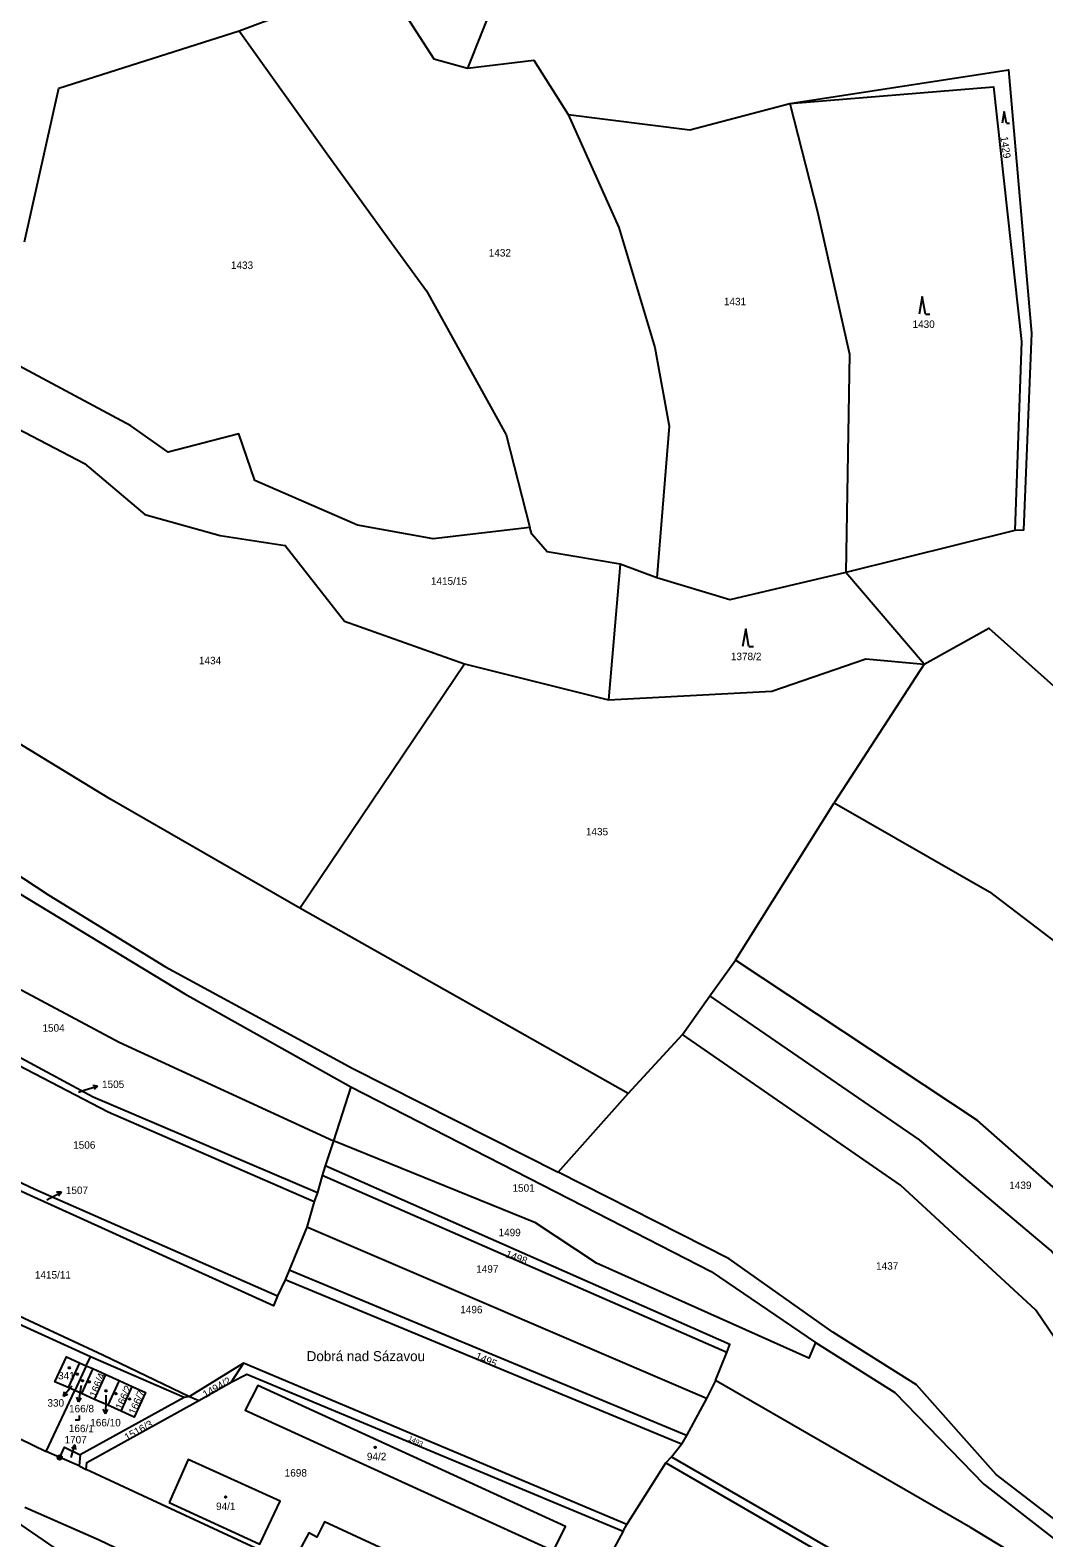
# Model space of a CAD drawing. Extents: x -680203 to -673936, y -1102717 to -1093650.
# Drawn here: x -675720.6 to -675489.7, y -1101094.1 to -1100750.7 of the extents above; entities that cross this region are included whole.
import ezdxf

# ---------------------------------------------------------------- set-up
doc = ezdxf.new("R2010")
doc.units = 0
for name, color, linetype in [('SOxx02xx_Koleje_param další_Popis10', 7, 'Continuous'), ('SOxx02xx_Staničení_Popis10', 7, 'Continuous'), ('SOxxxxxx_Koleje_hlavní_body_Popis10', 7, 'Continuous'), ('SOxxxxxx_Koleje_param další_Popis10', 7, 'Continuous'), ('SOxxxxxx_Osa_bod_P', 7, 'Continuous'), ('x_prac', 7, 'Continuous')]:
    doc.layers.add(name, color=color, linetype=linetype)

msp = doc.modelspace()

# ---------------------------------------------------------------- linework, layer by layer
at = {"layer": 'SOxx02xx_Koleje_param další_Popis10'}
for radius in [0.5, 0.0303]:
    msp.add_circle((-675713.86, -1101075.81), radius, dxfattribs=at)
at = {"layer": 'SOxx02xx_Staničení_Popis10'}
for p, q in [((-675708.09, -1100992.11), (-675705.22, -1100991.23)), ((-675705.22, -1100991.23), (-675706.32, -1100991.05)), ((-675705.22, -1100991.23), (-675706.03, -1100992)), ((-675709.61, -1100992.57), (-675708.09, -1100992.11)), ((-675716.12, -1101016.76), (-675713.45, -1101015.4)), ((-675713.45, -1101015.4), (-675714.57, -1101015.41)), ((-675713.45, -1101015.4), (-675714.11, -1101016.3)), ((-675716.76, -1101017.09), (-675716.12, -1101016.76)), ((-675711.08, -1101059.56), (-675713.01, -1101061.86)), ((-675709.13, -1101060.15), (-675709.6, -1101063.11)), ((-675709.01, -1101059.41), (-675709.13, -1101060.15)), ((-675713.01, -1101061.86), (-675712.75, -1101060.77)), ((-675713.01, -1101061.86), (-675711.98, -1101061.41)), ((-675709.6, -1101063.11), (-675709.94, -1101062.05)), ((-675709.6, -1101063.11), (-675708.95, -1101062.2)), ((-675703.39, -1101062.84), (-675703.44, -1101065.84)), ((-675703.38, -1101061.61), (-675703.39, -1101062.84)), ((-675703.44, -1101065.84), (-675703.93, -1101064.83)), ((-675703.44, -1101065.84), (-675702.92, -1101064.85)), ((-675711.26, -1101075.8), (-675710.43, -1101072.92)), ((-675710.43, -1101072.92), (-675711.19, -1101073.74)), ((-675710.43, -1101072.92), (-675710.23, -1101074.02))]:
    msp.add_line(p, q, dxfattribs=at)
at = {"layer": 'SOxxxxxx_Koleje_hlavní_body_Popis10'}
for p, q in [((-675498.75, -1100769.25), (-675499.25, -1100771.93)), ((-675498.25, -1100771.93), (-675498.75, -1100769.25)), ((-675498.25, -1100771.93), (-675497.58, -1100771.93)), ((-675517.41, -1100811.41), (-675518.16, -1100815.41)), ((-675516.66, -1100815.41), (-675517.41, -1100811.41)), ((-675516.66, -1100815.41), (-675515.66, -1100815.41)), ((-675557.63, -1100887.08), (-675558.38, -1100891.08)), ((-675556.88, -1100891.08), (-675557.63, -1100887.08)), ((-675556.88, -1100891.08), (-675555.88, -1100891.08)), ((-675710.34, -1101067.26), (-675709.34, -1101067.26)), ((-675709.34, -1101067.26), (-675709.34, -1101066.26))]:
    msp.add_line(p, q, dxfattribs=at)
at = {"layer": 'SOxxxxxx_Koleje_param další_Popis10'}
for centre in [(-675711.67, -1101055.39), (-675709.86, -1101056.83), (-675708.67, -1101058.34), (-675707.15, -1101058.59), (-675703.3, -1101060.63), (-675701.05, -1101061.26), (-675697.92, -1101062.49), (-675642.01, -1101073.52), (-675676.09, -1101084.79)]:
    msp.add_circle(centre, 0.175, dxfattribs=at)
at = {"layer": 'x_prac'}
for p, q in [((-675609.63, -1100730.63), (-675620.98, -1100759.39)), ((-675673, -1100750.89), (-675640.59, -1100738.69)), ((-675496.3, -1100864.7), (-675534.8, -1100874.26)), ((-675586.25, -1100872.36), (-675588.89, -1100903.27)), ((-675577.86, -1100875.43), (-675586.25, -1100872.36)), ((-675517.02, -1100895.11), (-675534.8, -1100874.26)), ((-675659.16, -1100950.66), (-675621.68, -1100895.07)), ((-675621.68, -1100895.07), (-675588.89, -1100903.27)), ((-675517.02, -1100895.11), (-675537.5, -1100926.67)), ((-675559.92, -1100962.52), (-675537.5, -1100926.67)), ((-675584.43, -1100992.93), (-675659.16, -1100950.66)), ((-675565.81, -1100970.64), (-675559.92, -1100962.52)), ((-675572, -1100979.5), (-675565.81, -1100970.64)), ((-675584.43, -1100992.93), (-675572, -1100979.5)), ((-675647.57, -1100991.38), (-675651.49, -1101003.7)), ((-675600.31, -1101010.82), (-675584.43, -1100992.93)), ((-675651.49, -1101003.7), (-675653.42, -1101009.42)), ((-675654.07, -1101011.58), (-675655.13, -1101015.48)), ((-675653.42, -1101009.42), (-675654.07, -1101011.58)), ((-675561.92, -1101051.92), (-675654.07, -1101011.58)), ((-675655.13, -1101015.48), (-675655.89, -1101017.51)), ((-675655.89, -1101017.51), (-675657.56, -1101023.38)), ((-675657.56, -1101023.38), (-675661.59, -1101033.11)), ((-675566.52, -1101062.35), (-675657.56, -1101023.38)), ((-675661.59, -1101033.11), (-675662.5, -1101035.34)), ((-675571.1, -1101070.82), (-675661.59, -1101033.11)), ((-675662.5, -1101035.34), (-675664.28, -1101038.98)), ((-675572.25, -1101072.79), (-675662.5, -1101035.34)), ((-675706.86, -1101052.91), (-675736.04, -1101039.58)), ((-675707.82, -1101054.9), (-675706.86, -1101052.91)), ((-675685.51, -1101062.14), (-675706.86, -1101052.91)), ((-675564.51, -1101058.29), (-675561.92, -1101051.92)), ((-675709.32, -1101054.22), (-675711.94, -1101059.9)), ((-675707.82, -1101054.9), (-675710.39, -1101060.59)), ((-675709.32, -1101054.22), (-675707.82, -1101054.9)), ((-675706.32, -1101055.58), (-675708.92, -1101061.24)), ((-675707.82, -1101054.9), (-675706.32, -1101055.58)), ((-675706.32, -1101055.58), (-675703.33, -1101056.94)), ((-675705.91, -1101062.58), (-675703.33, -1101056.94)), ((-675703.33, -1101056.94), (-675700.33, -1101058.31)), ((-675671.98, -1101054.33), (-675684.32, -1101061.92)), ((-675671.98, -1101054.33), (-675674.79, -1101058.69)), ((-675584.67, -1101091.09), (-675671.98, -1101054.33)), ((-675710.39, -1101060.59), (-675711.94, -1101059.9)), ((-675700.33, -1101058.31), (-675702.9, -1101063.92)), ((-675700.33, -1101058.31), (-675697.33, -1101059.67)), ((-675699.89, -1101065.26), (-675697.33, -1101059.67)), ((-675682.19, -1101062.83), (-675674.79, -1101058.69)), ((-675564.51, -1101058.29), (-675566.52, -1101062.35)), ((-675716.97, -1101074.45), (-675710.39, -1101060.59)), ((-675708.92, -1101061.24), (-675710.39, -1101060.59)), ((-675685.51, -1101062.14), (-675709.22, -1101075.21)), ((-675705.91, -1101062.58), (-675708.92, -1101061.24)), ((-675702.9, -1101063.92), (-675705.91, -1101062.58)), ((-675699.89, -1101065.26), (-675702.9, -1101063.92)), ((-675684.32, -1101061.92), (-675685.51, -1101062.14)), ((-675684.32, -1101061.92), (-675682.19, -1101062.83)), ((-675566.52, -1101062.35), (-675571.1, -1101070.82)), ((-675571.1, -1101070.82), (-675572.25, -1101072.79)), ((-675723.02, -1101071.47), (-675716.97, -1101074.45)), ((-675574.56, -1101075.67), (-675572.25, -1101072.79)), ((-675713.86, -1101075.81), (-675716.97, -1101074.45)), ((-675709.43, -1101077.74), (-675713.86, -1101075.81)), ((-675709.22, -1101075.21), (-675709.43, -1101077.74)), ((-675709.43, -1101077.74), (-675707.8, -1101078.55)), ((-675584.67, -1101091.09), (-675575.83, -1101077)), ((-675575.83, -1101077), (-675574.56, -1101075.67)), ((-675575.83, -1101077), (-675455.68, -1101146.63)), ((-675585.5, -1101092.56), (-675584.67, -1101091.09)), ((-675585.5, -1101092.56), (-675587.65, -1101096.54))]:
    msp.add_line(p, q, dxfattribs=at)
for points in [[(-675640.59, -1100738.69), (-675628.66, -1100757.28), (-675620.98, -1100759.39)], [(-675721.9, -1100798.89), (-675714.05, -1100763.89), (-675673, -1100750.89)], [(-675673, -1100750.89), (-675653.01, -1100778.82), (-675638.33, -1100799.17), (-675630.34, -1100810.08), (-675612.16, -1100842.92), (-675606.8, -1100863.98)], [(-675620.98, -1100759.39), (-675605.89, -1100757.56), (-675598.05, -1100769.95)], [(-675547.61, -1100767.39), (-675497.79, -1100759.76), (-675492.56, -1100819.75), (-675494.39, -1100864.59), (-675496.3, -1100864.7)], [(-675547.61, -1100767.39), (-675501.18, -1100763.62), (-675494.83, -1100821.61), (-675496.3, -1100864.7)], [(-675598.05, -1100769.95), (-675570.34, -1100773.4), (-675547.61, -1100767.39)], [(-675547.61, -1100767.39), (-675541.31, -1100792.07), (-675533.99, -1100824.54), (-675534.8, -1100874.26)], [(-675598.05, -1100769.95), (-675586.49, -1100795.66), (-675578.29, -1100823.01), (-675575.05, -1100840.95), (-675577.86, -1100875.43)], [(-675606.8, -1100863.98), (-675628.8, -1100866.56), (-675646.06, -1100863.47), (-675669.4, -1100853.27), (-675673.09, -1100842.69), (-675689.19, -1100846.84), (-675697.69, -1100840.87), (-675726.26, -1100825.48)], [(-675725.19, -1100840.51), (-675708.22, -1100849.41), (-675694.5, -1100861), (-675677.34, -1100865.81), (-675662.52, -1100868.06), (-675649, -1100885.33), (-675621.68, -1100895.07)], [(-675586.25, -1100872.36), (-675602.85, -1100869.52), (-675606.3, -1100865.52), (-675606.8, -1100863.98)], [(-675827.85, -1100874.34), (-675809.84, -1100886.24), (-675716.31, -1100947.76), (-675689.79, -1100964.06), (-675647.08, -1100987.2), (-675600.31, -1101010.82)], [(-675534.8, -1100874.26), (-675561.23, -1100880.46), (-675577.86, -1100875.43)], [(-675517.02, -1100895.11), (-675502.29, -1100886.93), (-675469.39, -1100916.25)], [(-675813.31, -1100889.18), (-675732.87, -1100941.41), (-675685.35, -1100970.17), (-675647.57, -1100991.38)], [(-675659.16, -1100950.66), (-675702.41, -1100925.76), (-675758.38, -1100891.71)], [(-675588.89, -1100903.27), (-675551.65, -1100901.25), (-675530.27, -1100893.94), (-675517.02, -1100895.11)], [(-675828, -1100913.03), (-675700.31, -1100981.21), (-675651.49, -1101003.7)], [(-675835.74, -1100923.83), (-675706.23, -1100993.68), (-675655.13, -1101015.48)], [(-675537.5, -1100926.67), (-675502.07, -1100946.99), (-675438.48, -1100995.48), (-675419.75, -1101020.52), (-675416.3, -1101027.47)], [(-675432.51, -1101126.7), (-675433.51, -1101115.03), (-675437.49, -1101096.28), (-675444.56, -1101076.11), (-675455.49, -1101053.21), (-675474.23, -1101026.02), (-675504.82, -1100999.06), (-675559.92, -1100962.52)], [(-675443.9, -1101120.86), (-675445.88, -1101107.19), (-675453.94, -1101082.75), (-675465.44, -1101059.9), (-675483.33, -1101034.25), (-675488.19, -1101028.61), (-675518.05, -1101003.45), (-675565.81, -1100970.64)], [(-675742.01, -1100976.73), (-675702.84, -1100997.07), (-675655.89, -1101017.51)], [(-675454.74, -1101114.88), (-675464.06, -1101088.53), (-675472.23, -1101070.83), (-675491.54, -1101042.28), (-675522.4, -1101013.8), (-675572, -1100979.5)], [(-675647.57, -1100991.38), (-675591.5, -1101020.05), (-675565.5, -1101033.42), (-675541.71, -1101049.65)], [(-675664.28, -1101038.98), (-675665.16, -1101041.29), (-675721.41, -1101015.78), (-675754.22, -1101000.41)], [(-675753.26, -1100998.79), (-675719.54, -1101014.69), (-675664.28, -1101038.98)], [(-675541.71, -1101049.65), (-675543.28, -1101053.18), (-675591.61, -1101031.53), (-675605.54, -1101022.36), (-675651.49, -1101003.7)], [(-675561.92, -1101051.92), (-675561.25, -1101050.08), (-675653.42, -1101009.42)], [(-675454.74, -1101114.88), (-675500.55, -1101079.65), (-675518.75, -1101059.25), (-675537.79, -1101047.23), (-675561.38, -1101030.55), (-675600.31, -1101010.82)], [(-675773.7, -1101019.91), (-675735.43, -1101037.86), (-675704.04, -1101052.44), (-675684.32, -1101061.92)], [(-675541.71, -1101049.65), (-675523.67, -1101061.03), (-675503.36, -1101081.92), (-675460.22, -1101115.51)], [(-675711.94, -1101059.9), (-675714.95, -1101058.55), (-675712.32, -1101052.86), (-675709.32, -1101054.22)], [(-675674.79, -1101058.69), (-675671.23, -1101056.8), (-675585.5, -1101092.56)], [(-675697.33, -1101059.67), (-675694.34, -1101061.03), (-675696.88, -1101066.6), (-675699.89, -1101065.26)], [(-675601.4, -1101097.06), (-675598.7, -1101091.54), (-675668.72, -1101059.43), (-675671.61, -1101065.02), (-675601.4, -1101097.06)], [(-675460.22, -1101115.51), (-675462.69, -1101118.33), (-675506.43, -1101091.77), (-675564.51, -1101058.29)], [(-675707.8, -1101078.55), (-675707.67, -1101076.99), (-675682.19, -1101062.83)], [(-675713.86, -1101075.81), (-675712.74, -1101073.47), (-675709.22, -1101075.21)], [(-675688.94, -1101086.04), (-675668.28, -1101095.58), (-675663.62, -1101085.75), (-675684.6, -1101076.3), (-675688.94, -1101086.04)], [(-675574.56, -1101075.67), (-675454.74, -1101144.93), (-675455.68, -1101146.63)], [(-675600.1, -1101125.14), (-675601.45, -1101127.96), (-675707.8, -1101078.55)], [(-675721.84, -1101087.16), (-675704.85, -1101094.6), (-675691.05, -1101101.14), (-675677.91, -1101107.11), (-675656.98, -1101117.13), (-675640.38, -1101124.41), (-675592.13, -1101148.74), (-675586.77, -1101151.17), (-675563.66, -1101162.44)], [(-675707.01, -1101098.72), (-675713.92, -1101097.12), (-675723.82, -1101090.33)], [(-675642.09, -1101107.57), (-675640.57, -1101104.62), (-675637.71, -1101106.01), (-675635.93, -1101102.51), (-675638.62, -1101101.12), (-675637.04, -1101098.14), (-675653.52, -1101090.5), (-675655.29, -1101093.94), (-675657.16, -1101092.99), (-675658.88, -1101096.21), (-675657, -1101097.24), (-675658.49, -1101100.07), (-675642.09, -1101107.57)]]:
    msp.add_lwpolyline(points, dxfattribs=at)

# ---------------------------------------------------------------- texts
at = {"layer": 'SOxx02xx_Staničení_Popis10'}
msp.add_text('Dobrá nad Sázavou', height=2.28, dxfattribs=at).set_placement((-675657.61, -1101053.87))
at = {"layer": 'SOxxxxxx_Osa_bod_P'}
for s, height, rotation, p in [('1429', 1.7, 278, (-675499.63, -1100775.02)), ('1498', 1.7, 339, (-675612.47, -1101030.11)), ('1495', 1.7, 336, (-675619.37, -1101053.32)), ('166/4', 1.7, 68, (-675705.57, -1101062.27)), ('166/2', 1.7, 66, (-675699.7, -1101065.09)), ('166/7', 1.7, 66, (-675696.69, -1101066.17)), ('1494/2', 1.7, 30, (-675680.68, -1101062.34)), ('1516/3', 1.7, 29, (-675698.55, -1101072.08)), ('166/1', 1.7, 359, (-675711.79, -1101069.99)), ('1493', 1.14, 335, (-675634.61, -1101071.88))]:
    msp.add_text(s, height=height, rotation=rotation, dxfattribs=at).set_placement(p)
for s, p in [('1432', (-675616.15, -1100802.27)), ('1433', (-675674.87, -1100805.1)), ('1431', (-675562.6, -1100813.38)), ('1430', (-675519.64, -1100818.53)), ('1415/15', (-675629.32, -1100877.04)), ('1434', (-675682.16, -1100895.14)), ('1378/2', (-675561, -1100894.21)), ('1435', (-675594.03, -1100934.11)), ('1504', (-675717.79, -1100978.83)), ('1505', (-675704.22, -1100991.66)), ('1506', (-675710.8, -1101005.49)), ('1507', (-675712.46, -1101015.8)), ('1501', (-675610.74, -1101015.28)), ('1439', (-675497.6, -1101014.66)), ('1499', (-675613.92, -1101025.42)), ('1497', (-675619, -1101033.74)), ('1437', (-675527.93, -1101033.03)), ('1415/11', (-675719.52, -1101035.07)), ('1496', (-675622.63, -1101042.97)), ('341', (-675714.24, -1101058.02)), ('330', (-675716.66, -1101064.23)), ('166/8', (-675711.74, -1101065.53)), ('166/10', (-675706.91, -1101068.72)), ('1707', (-675712.77, -1101072.61)), ('94/2', (-675643.9, -1101076.44)), ('1698', (-675662.62, -1101080.16)), ('94/1', (-675678.25, -1101087.78))]:
    msp.add_text(s, height=1.7, dxfattribs=at).set_placement(p)

doc.saveas('drawing.dxf')
